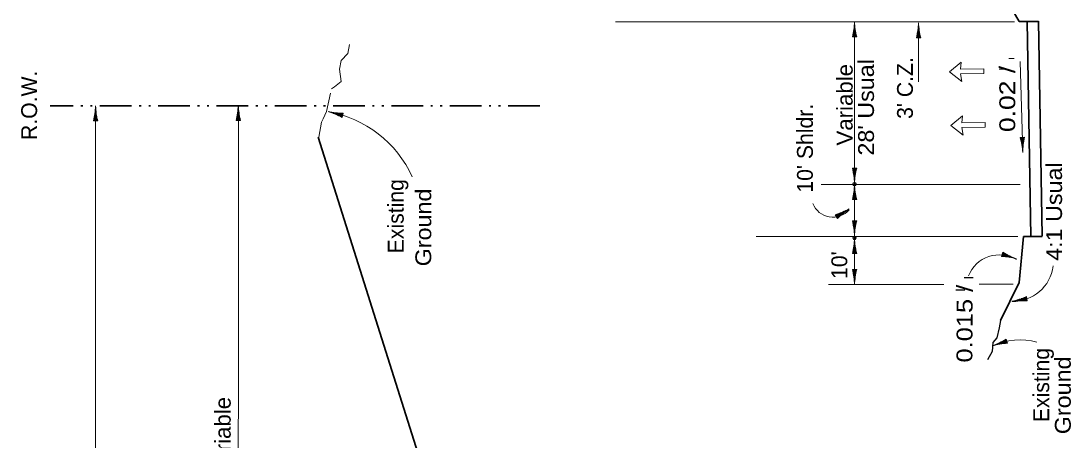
# Model space of a CAD drawing. Extents: x 2363427 to 2368559, y 6957299 to 6980140.
# Drawn here: x 2363641 to 2364569, y 6964238 to 6964609 of the extents above; entities that cross this region are included whole.
import ezdxf
from ezdxf.enums import TextEntityAlignment as Align

# ---------------------------------------------------------------- set-up
doc = ezdxf.new("R2010")
doc.units = 0
doc.header["$LTSCALE"] = 5.6
doc.header["$PDMODE"] = 32
doc.header["$PDSIZE"] = 2.8
doc.linetypes.add('DASH_DOUBLE_DOT', pattern=[9.2, 5, -1.2, 0.3, -1.2, 0.3, -1.2])
doc.linetypes.add('MEDIUM_DASHED', pattern=[4.5, 3, -1.5])
for name, color, linetype, lineweight in [('1', 7, 'Continuous', 13), ('3', 7, 'Continuous', 35), ('4', 7, 'Continuous', 13), ('40', 7, 'Continuous', 35), ('48', 7, 'Continuous', 25), ('6', 7, 'Continuous', 13), ('8', 7, 'Continuous', 13)]:
    doc.layers.add(name, color=color, linetype=linetype, lineweight=lineweight)

msp = doc.modelspace()

# ---------------------------------------------------------------- linework, layer by layer
at = {"layer": '1'}
for p, q in [((2364434.045, 6964594.33), (2364434.045, 6964606.894)), ((2364433.045, 6964594.33), (2364433.045, 6964598.606)), ((2364433.545, 6964594.33), (2364433.545, 6964601.68)), ((2364434.545, 6964594.33), (2364434.545, 6964602.94)), ((2364435.045, 6964594.33), (2364435.045, 6964599.192)), ((2364435.545, 6964594.33), (2364435.545, 6964596.712)), ((2364432.195, 6964594.33), (2364436.025, 6964594.33)), ((2364432.545, 6964594.33), (2364432.545, 6964595.916)), ((2363925.259, 6964525.841), (2363913.088, 6964528.963)), ((2363925.134, 6964525.357), (2363916.795, 6964527.495)), ((2363925.383, 6964526.325), (2363918.264, 6964528.151)), ((2363925.01, 6964524.872), (2363920.301, 6964526.08)), ((2363925.507, 6964526.809), (2363921.365, 6964527.872)), ((2363924.886, 6964524.387), (2363922.579, 6964524.979)), ((2363925.632, 6964527.293), (2363924.096, 6964527.687)), ((2363925.718, 6964527.633), (2363924.767, 6964523.923))]:
    msp.add_line(p, q, dxfattribs=at)
at = {"layer": '1', "linetype": 'MEDIUM_DASHED'}
msp.add_lwpolyline([(2363904.008, 6964506.629), (2363906.45, 6964519.711), (2363907.91, 6964522.83), (2363910.828, 6964529.067), (2363915.205, 6964549.338), (2363918.123, 6964550.897), (2363923.96, 6964555.575), (2363922.5, 6964566.491), (2363923.96, 6964574.287), (2363929.796, 6964580.525), (2363931.255, 6964588.321)], dxfattribs=at)
at = {"layer": '1', "linetype": 'MEDIUM_DASHED', "lineweight": 25}
msp.add_lwpolyline([(2364506.602, 6964344.488), (2364505.25, 6964337.986), (2364503.222, 6964329.316), (2364499.842, 6964324.982), (2364499.166, 6964317.034), (2364495.11, 6964309.81)], dxfattribs=at)
at = {"layer": '1'}
for centre, radius, start, end in [((2364361.987, 6964611.224), 72.212, 346.47039, 357.15644), ((2364506.234, 6964611.224), 72.212, 182.84356, 193.52961), ((2363895.513, 6964430.595), 99.89, 24.09271, 80.33269), ((2363890.958, 6964460.114), 72.212, 62.08378, 72.76982), ((2363926.799, 6964599.837), 72.212, 258.45694, 269.14299)]:
    msp.add_arc(centre, radius, start, end, dxfattribs=at)
at = {"layer": '3'}
for p, q in [((2364523.11, 6964608.848), (2364344.609, 6964912.542)), ((2364540.133, 6964608.849), (2364523.11, 6964608.848)), ((2364533.453, 6964418.814), (2364530.132, 6964608.849)), ((2364543.451, 6964418.923), (2364540.131, 6964608.936)), ((2363903.486, 6964506.464), (2364078.165, 6963954.849)), ((2364526.861, 6964418.785), (2364523.005, 6964378.02)), ((2364526.861, 6964418.785), (2364543.453, 6964418.857)), ((2364523.005, 6964378.021), (2364506.602, 6964344.489))]:
    msp.add_line(p, q, dxfattribs=at)
at = {"layer": '3', "linetype": 'DASH_DOUBLE_DOT'}
msp.add_line((2364099.338, 6964534.119), (2363666.685, 6964534.185), dxfattribs=at)
at = {"layer": '4'}
for p, q in [((2364518.821, 6964608.464), (2364166.319, 6964608.464)), ((2364377.539, 6964608.48), (2364377.539, 6964376.247)), ((2364377.603, 6964595.168), (2364377.603, 6964607.732)), ((2364377.603, 6964595.168), (2364377.603, 6964607.732)), ((2364434.11, 6964607.642), (2364434.11, 6964555.28)), ((2364376.103, 6964595.168), (2364376.103, 6964597.55)), ((2364376.103, 6964595.168), (2364376.103, 6964597.55)), ((2364376.603, 6964595.168), (2364376.603, 6964600.03)), ((2364376.603, 6964595.168), (2364376.603, 6964600.03)), ((2364377.103, 6964595.168), (2364377.103, 6964603.778)), ((2364377.103, 6964595.168), (2364377.103, 6964603.778)), ((2364378.103, 6964595.168), (2364378.103, 6964602.518)), ((2364378.103, 6964595.168), (2364378.103, 6964602.518)), ((2364378.603, 6964595.168), (2364378.603, 6964599.445)), ((2364378.603, 6964595.168), (2364378.603, 6964599.445)), ((2364379.103, 6964595.168), (2364379.103, 6964596.754)), ((2364379.103, 6964595.168), (2364379.103, 6964596.754)), ((2364379.453, 6964595.168), (2364375.623, 6964595.168)), ((2364379.453, 6964595.168), (2364375.623, 6964595.168)), ((2364523.925, 6964573.294), (2364526.201, 6964493.04)), ((2364527.737, 6964506.401), (2364523.909, 6964506.292)), ((2364524.389, 6964506.306), (2364524.457, 6964503.926)), ((2364524.889, 6964506.32), (2364525.027, 6964501.46)), ((2364525.389, 6964506.334), (2364525.633, 6964497.728)), ((2364525.888, 6964506.348), (2364526.245, 6964493.79)), ((2364526.388, 6964506.362), (2364526.597, 6964499.016)), ((2364526.888, 6964506.377), (2364527.009, 6964502.102)), ((2364527.387, 6964506.391), (2364527.433, 6964504.806)), ((2364375.623, 6964479.082), (2364379.453, 6964479.082)), ((2364375.623, 6964479.082), (2364379.453, 6964479.082)), ((2364375.973, 6964479.082), (2364375.973, 6964477.498)), ((2364375.973, 6964479.082), (2364375.973, 6964477.498)), ((2364376.473, 6964479.082), (2364376.473, 6964474.806)), ((2364376.473, 6964479.082), (2364376.473, 6964474.806)), ((2364376.973, 6964479.082), (2364376.973, 6964471.732)), ((2364376.973, 6964479.082), (2364376.973, 6964471.732)), ((2364377.473, 6964479.082), (2364377.473, 6964466.518)), ((2364377.473, 6964479.082), (2364377.473, 6964466.518)), ((2364377.973, 6964479.082), (2364377.973, 6964470.473)), ((2364377.973, 6964479.082), (2364377.973, 6964470.473)), ((2364378.473, 6964479.082), (2364378.473, 6964474.22)), ((2364378.473, 6964479.082), (2364378.473, 6964474.22)), ((2364378.973, 6964479.082), (2364378.973, 6964476.701)), ((2364378.973, 6964479.082), (2364378.973, 6964476.701)), ((2364523.886, 6964464.785), (2364348.018, 6964464.785)), ((2364377.103, 6964451.433), (2364377.103, 6964460.043)), ((2364377.103, 6964451.433), (2364377.103, 6964460.043)), ((2364377.603, 6964451.433), (2364377.603, 6964463.997)), ((2364377.603, 6964451.433), (2364377.603, 6964463.997)), ((2364378.103, 6964451.433), (2364378.103, 6964458.783)), ((2364378.103, 6964451.433), (2364378.103, 6964458.783)), ((2364379.453, 6964451.433), (2364375.623, 6964451.433)), ((2364379.453, 6964451.433), (2364375.623, 6964451.433)), ((2364376.103, 6964451.433), (2364376.103, 6964453.815)), ((2364376.103, 6964451.433), (2364376.103, 6964453.815)), ((2364376.603, 6964451.433), (2364376.603, 6964456.295)), ((2364376.603, 6964451.433), (2364376.603, 6964456.295)), ((2364378.603, 6964451.433), (2364378.603, 6964455.71)), ((2364378.603, 6964451.433), (2364378.603, 6964455.71)), ((2364379.103, 6964451.433), (2364379.103, 6964453.019)), ((2364379.103, 6964451.433), (2364379.103, 6964453.019)), ((2364360.663, 6964437.491), (2364362.698, 6964438.727)), ((2364360.922, 6964437.065), (2364365.078, 6964439.587)), ((2364361.181, 6964436.637), (2364368.541, 6964441.105)), ((2364361.441, 6964436.209), (2364372.181, 6964442.729)), ((2364361.7, 6964435.782), (2364367.983, 6964439.596)), ((2364362.401, 6964434.628), (2364360.413, 6964437.902)), ((2364361.959, 6964435.355), (2364365.615, 6964437.573)), ((2364362.219, 6964434.927), (2364363.574, 6964435.75)), ((2364375.623, 6964432.604), (2364379.453, 6964432.604)), ((2364375.623, 6964432.604), (2364379.453, 6964432.604)), ((2364375.973, 6964432.604), (2364375.973, 6964431.02)), ((2364375.973, 6964432.604), (2364375.973, 6964431.02)), ((2364376.473, 6964432.604), (2364376.473, 6964428.328)), ((2364376.473, 6964432.604), (2364376.473, 6964428.328)), ((2364376.973, 6964432.604), (2364376.973, 6964425.254)), ((2364376.973, 6964432.604), (2364376.973, 6964425.254)), ((2364377.473, 6964432.604), (2364377.473, 6964420.04)), ((2364377.473, 6964432.604), (2364377.473, 6964420.04)), ((2364377.973, 6964432.604), (2364377.973, 6964423.995)), ((2364377.973, 6964432.604), (2364377.973, 6964423.995)), ((2364378.473, 6964432.604), (2364378.473, 6964427.742)), ((2364378.473, 6964432.604), (2364378.473, 6964427.742)), ((2364378.973, 6964432.604), (2364378.973, 6964430.223)), ((2364378.973, 6964432.604), (2364378.973, 6964430.223)), ((2364521.957, 6964418.721), (2364290.628, 6964418.721)), ((2364377.103, 6964403.837), (2364377.103, 6964412.447)), ((2364377.103, 6964403.837), (2364377.103, 6964412.447)), ((2364377.603, 6964403.837), (2364377.603, 6964416.401)), ((2364377.603, 6964403.837), (2364377.603, 6964416.401)), ((2364378.103, 6964403.837), (2364378.103, 6964411.187)), ((2364378.103, 6964403.837), (2364378.103, 6964411.187)), ((2364379.453, 6964403.837), (2364375.623, 6964403.837)), ((2364379.453, 6964403.837), (2364375.623, 6964403.837)), ((2364376.103, 6964403.837), (2364376.103, 6964406.219)), ((2364376.103, 6964403.837), (2364376.103, 6964406.219)), ((2364376.603, 6964403.837), (2364376.603, 6964408.699)), ((2364376.603, 6964403.837), (2364376.603, 6964408.699)), ((2364378.603, 6964403.837), (2364378.603, 6964408.114)), ((2364378.603, 6964403.837), (2364378.603, 6964408.114)), ((2364379.103, 6964403.837), (2364379.103, 6964405.423)), ((2364379.103, 6964403.837), (2364379.103, 6964405.423)), ((2364507.482, 6964401.208), (2364508.647, 6964404.857)), ((2364507.589, 6964401.541), (2364509.099, 6964401.059)), ((2364507.741, 6964402.018), (2364511.815, 6964400.717)), ((2364507.893, 6964402.494), (2364514.894, 6964400.257)), ((2364508.045, 6964402.971), (2364520.013, 6964399.147)), ((2364508.197, 6964403.447), (2364516.399, 6964400.827)), ((2364508.349, 6964403.923), (2364512.981, 6964402.443)), ((2364508.501, 6964404.399), (2364510.77, 6964403.675)), ((2364375.644, 6964389.644), (2364379.474, 6964389.644)), ((2364375.644, 6964389.644), (2364379.474, 6964389.644)), ((2364375.994, 6964389.644), (2364375.994, 6964388.06)), ((2364375.994, 6964389.644), (2364375.994, 6964388.06)), ((2364376.494, 6964389.644), (2364376.494, 6964385.368)), ((2364376.494, 6964389.644), (2364376.494, 6964385.368)), ((2364376.994, 6964389.644), (2364376.994, 6964382.294)), ((2364376.994, 6964389.644), (2364376.994, 6964382.294)), ((2364377.494, 6964389.644), (2364377.494, 6964377.08)), ((2364377.494, 6964389.644), (2364377.494, 6964377.08)), ((2364377.994, 6964389.644), (2364377.994, 6964381.035)), ((2364377.994, 6964389.644), (2364377.994, 6964381.035)), ((2364378.494, 6964389.644), (2364378.494, 6964384.782)), ((2364378.494, 6964389.644), (2364378.494, 6964384.782)), ((2364378.994, 6964389.644), (2364378.994, 6964387.263)), ((2364378.994, 6964389.644), (2364378.994, 6964387.263)), ((2364456.478, 6964376.247), (2364354.601, 6964376.247)), ((2364517.71, 6964376.636), (2364487.635, 6964376.636)), ((2364529.61, 6964364.687), (2364524.82, 6964363.849)), ((2364529.524, 6964365.179), (2364527.178, 6964364.769)), ((2364530.102, 6964361.88), (2364529.442, 6964365.652)), ((2364529.782, 6964363.701), (2364517.406, 6964361.536)), ((2364529.696, 6964364.195), (2364521.216, 6964362.711)), ((2364529.869, 6964363.209), (2364522.628, 6964361.942)), ((2364529.955, 6964362.717), (2364525.742, 6964361.979)), ((2364530.041, 6964362.225), (2364528.48, 6964361.951)), ((2364511.75, 6964327.307), (2364507.684, 6964325.981)), ((2364511.595, 6964327.783), (2364510.088, 6964327.291)), ((2364511.487, 6964328.115), (2364512.673, 6964324.473)), ((2364512.06, 6964326.356), (2364500.115, 6964322.462)), ((2364512.215, 6964325.881), (2364504.029, 6964323.213)), ((2364511.905, 6964326.831), (2364504.917, 6964324.553)), ((2364512.37, 6964325.405), (2364507.747, 6964323.899)), ((2364512.525, 6964324.93), (2364510.261, 6964324.192))]:
    msp.add_line(p, q, dxfattribs=at)
at = {"layer": '4', "lineweight": 25}
for p, q in [((2364482.47, 6964382.283), (2364474.309, 6964382.283)), ((2364475.152, 6964371.459), (2364466.992, 6964371.459))]:
    msp.add_line(p, q, dxfattribs=at)
at = {"layer": '4'}
for centre, radius, start, end in [((2364305.415, 6964612.062), 72.212, 346.47039, 357.15644), ((2364305.415, 6964612.062), 72.212, 346.47039, 357.15644), ((2364449.662, 6964612.062), 72.212, 182.84356, 193.52961), ((2364449.662, 6964612.062), 72.212, 182.84356, 193.52961), ((2364454.207, 6964487.416), 72.212, 4.46769, 15.15374), ((2364598.396, 6964491.504), 72.212, 168.09453, 178.78057), ((2364305.415, 6964462.188), 72.212, 2.84356, 13.52961), ((2364305.415, 6964462.188), 72.212, 2.84356, 13.52961), ((2364449.662, 6964462.188), 72.212, 166.47039, 177.15644), ((2364449.662, 6964462.188), 72.212, 166.47039, 177.15644), ((2364305.415, 6964468.328), 72.212, 346.47039, 357.15644), ((2364305.415, 6964468.328), 72.212, 346.47039, 357.15644), ((2364449.662, 6964468.328), 72.212, 182.84356, 193.52961), ((2364449.662, 6964468.328), 72.212, 182.84356, 193.52961), ((2364358.408, 6964454.63), 18.823, 200.84978, 319.74384), ((2364338.422, 6964506.684), 72.212, 287.73061, 298.41666), ((2364413.275, 6964383.379), 72.212, 124.10378, 134.78983), ((2364305.415, 6964415.711), 72.212, 2.84356, 13.52961), ((2364305.415, 6964415.711), 72.212, 2.84356, 13.52961), ((2364449.662, 6964415.711), 72.212, 166.47039, 177.15644), ((2364449.662, 6964415.711), 72.212, 166.47039, 177.15644), ((2364305.415, 6964420.731), 72.212, 346.47039, 357.15644), ((2364305.415, 6964420.731), 72.212, 346.47039, 357.15644), ((2364449.662, 6964420.731), 72.212, 182.84356, 193.52961), ((2364449.662, 6964420.731), 72.212, 182.84356, 193.52961), ((2364505.725, 6964372.919), 29.635, 59.62074, 157.81619), ((2364546.106, 6964466.594), 72.212, 238.75343, 249.43948), ((2364502.21, 6964329.188), 72.212, 75.12659, 85.81264), ((2364517.456, 6964397.375), 36.023, 268.88537, 352.71261), ((2364305.436, 6964372.751), 72.212, 2.84356, 13.52961), ((2364305.436, 6964372.751), 72.212, 2.84356, 13.52961), ((2364449.683, 6964372.751), 72.212, 166.47039, 177.15644), ((2364449.683, 6964372.751), 72.212, 166.47039, 177.15644), ((2364500.698, 6964431.898), 72.212, 282.77005, 293.4561), ((2364525.563, 6964289.811), 72.212, 86.39688, 97.08293), ((2364523.325, 6964270.669), 56.809, 74.22951, 114.90949), ((2364473.664, 6964389.63), 72.212, 290.89929, 301.58534), ((2364518.373, 6964252.487), 72.212, 94.52612, 105.21217)]:
    msp.add_arc(centre, radius, start, end, dxfattribs=at)
for p in [(2364377.539, 6964477.567), (2364377.539, 6964465.146), (2364377.539, 6964464.745), (2364377.539, 6964417.55), (2364377.539, 6964417.149)]:
    msp.add_point(p, dxfattribs=at)
at = {"layer": '40', "lineweight": 13}
for p, q in [((2364471.212, 6964566.578), (2364491.717, 6964566.773)), ((2364472.397, 6964519.185), (2364492.903, 6964519.38))]:
    msp.add_line(p, q, dxfattribs=at)
for points in [[(2364471.212, 6964566.578), (2364471.745, 6964572.893), (2364461.357, 6964564.358), (2364472.457, 6964555.755), (2364471.249, 6964562.483)], [(2364471.249, 6964562.483), (2364491.755, 6964562.678), (2364491.717, 6964566.773)], [(2364472.397, 6964519.185), (2364472.93, 6964525.5), (2364462.543, 6964516.965), (2364473.643, 6964508.363), (2364472.435, 6964515.09)], [(2364472.435, 6964515.09), (2364492.94, 6964515.285), (2364492.903, 6964519.38)]]:
    msp.add_lwpolyline(points, dxfattribs=at)
at = {"layer": '48', "lineweight": 13}
for p, q in [((2364513.922, 6964576.096), (2364518.691, 6964576.096)), ((2364510.99, 6964566.74), (2364505.267, 6964566.74))]:
    msp.add_line(p, q, dxfattribs=at)
msp.add_lwpolyline([(2364533.453, 6964418.814), (2364543.451, 6964418.923), (2364540.131, 6964608.936), (2364530.132, 6964608.849)], close=True, dxfattribs=at)
at = {"layer": '6'}
for p, q in [((2363706.866, 6963654.512), (2363706.86, 6964534.136)), ((2363706.925, 6964520.825), (2363706.925, 6964533.389)), ((2363833.027, 6964521.302), (2363833.027, 6964533.866)), ((2363705.425, 6964520.825), (2363705.425, 6964523.206)), ((2363705.925, 6964520.825), (2363705.925, 6964525.687)), ((2363706.425, 6964520.825), (2363706.425, 6964529.434)), ((2363707.425, 6964520.825), (2363707.425, 6964528.175)), ((2363707.925, 6964520.825), (2363707.925, 6964525.101)), ((2363708.425, 6964520.825), (2363708.425, 6964522.41)), ((2363831.527, 6964521.302), (2363831.527, 6964523.683)), ((2363832.027, 6964521.302), (2363832.027, 6964526.164)), ((2363832.527, 6964521.302), (2363832.527, 6964529.911)), ((2363833.527, 6964521.302), (2363833.527, 6964528.652)), ((2363834.027, 6964521.302), (2363834.027, 6964525.578)), ((2363834.527, 6964521.302), (2363834.527, 6964522.887)), ((2363708.775, 6964520.825), (2363704.945, 6964520.825)), ((2363834.877, 6964521.302), (2363831.047, 6964521.302))]:
    msp.add_line(p, q, dxfattribs=at)
msp.add_lwpolyline([(2363833.002, 6963985.363), (2363832.925, 6963985.791), (2363833.074, 6964529.108)], dxfattribs=at)
for centre, start, end in [((2363634.737, 6964537.719), 346.47039, 357.15644), ((2363778.984, 6964537.719), 182.84356, 193.52961), ((2363760.839, 6964538.196), 346.47039, 357.15644), ((2363905.086, 6964538.196), 182.84356, 193.52961)]:
    msp.add_arc(centre, 72.212, start, end, dxfattribs=at)
at = {"layer": '8'}
for points in [[(2364461.357, 6964564.358), (2364471.745, 6964572.893), (2364471.212, 6964566.578), (2364491.717, 6964566.773), (2364491.755, 6964562.678), (2364471.249, 6964562.483), (2364472.457, 6964555.755)], [(2364462.543, 6964516.965), (2364472.93, 6964525.5), (2364472.397, 6964519.185), (2364492.903, 6964519.38), (2364492.94, 6964515.285), (2364472.435, 6964515.09), (2364473.643, 6964508.363)]]:
    msp.add_lwpolyline(points, close=True, dxfattribs=at)

# ---------------------------------------------------------------- texts
at = {"layer": '4'}
for s, rotation, width, p in [('Variable', 90, 1.05, (2364375.899, 6964535.167)), ("28' Usual", 90, 1.1, (2364394.74, 6964532.861)), ('0.02 /', 90, 1.25, (2364519.544, 6964540.292)), ('4:1 Usual', 90.006, 1.1, (2364560.912, 6964440.768)), ('Ground', 90, 1.1, (2364003.468, 6964426.753)), ('0.015 /', 89.708, 1.2, (2364481.83, 6964341.713)), ('Ground', 90, 1.1, (2364568.66, 6964278.384)), ('Variable', 90, 1.05, (2363826.258, 6964240.958))]:
    msp.add_text(s, height=14, rotation=rotation, dxfattribs=dict(at, width=width)).set_placement(p, align=Align.CENTER)
for s, p in [("3' C.Z.", (2364429.124, 6964549.963)), ('R.O.W.', (2363655.161, 6964534.679)), ("10' Shldr.", (2364340.725, 6964496.769)), ('Existing ', (2363979.124, 6964439.287)), ("10' ", (2364371.107, 6964396.049)), ('Existing ', (2364549.569, 6964290.105))]:
    msp.add_text(s, height=14, rotation=90, dxfattribs=at).set_placement(p, align=Align.CENTER)

doc.saveas('drawing.dxf')
